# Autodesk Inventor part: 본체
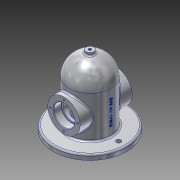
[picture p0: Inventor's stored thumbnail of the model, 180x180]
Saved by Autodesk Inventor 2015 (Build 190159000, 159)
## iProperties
Created: 2019-11
Part Number: 본체
Material: 알루미늄 6061
Document SubType Name: Modeling
Designer: Line503_02
Density: 2.7 g/cm^3
Appearance: 알루미늄 - 평지
Mass: 1106.12 g
Surface Area: 883.263 cm^2
Volume: 409.676 cm^3
Author: Line503_02
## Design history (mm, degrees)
sketch "스케치1"
  geometry: C1 r 70 at (0, 0); 1 further point
  constraints: 1 centre point, 1 coincident
  dimensions: "d0" = 140 diameter of C1
extrude "돌출1" new body sketch "스케치1" distance "d1" = 10; taper "d2" = 0 deg
sketch "스케치2"
  geometry: C1 r 40 at (0, 0); 1 further point
  constraints: 1 centre point, 1 coincident
  dimensions: "d3" = 80 diameter of C1
extrude "돌출2" join sketch "스케치2" distance "d4" = 80; taper "d5" = 0 deg
sketch "스케치3"
  geometry: L1 (40, 90)-(-40, 90) reference; L2 (0, 130)-(0, 90); L3 (40, 90)-(0, 90); A1 r 40 centre (0, 90) between (40, 90) and (0, 130); 1 further point
  constraints: 5 end point, 2 point on circle, 1 centre point, 1 midpoint, 1 perpendicular, 1 vertical
revolve "회전1" sketch "스케치3" stored, may be unused: angle "d6" = 90 deg
sketch "스케치4"
  geometry: L1 (-50, 81)-(50, 81); L2 (50, 81)-(50, 50); L3 (50, 50)-(-50, 50); L4 (-50, 50)-(-50, 81); 1 further point
  constraints: 8 end point, 2 parallel, 1 horizontal, 1 perpendicular
  dimensions: "d7" = 50 distance from line of L3 point (0, 0); "d8" = 100 distance of L2.end L3.end; "d9" = 50 distance from line of point (0, 0) L4; "d10" = 62 diameter of L1 L3
revolve "회전2" sketch "스케치4" stored, may be unused: angle "d11" = 90 deg
sketch "스케치5"
  geometry: L1 (40, 10)-(40, 90) reference; L2 (0, 0)-(0, 120); L3 (0, 0)-(30, 0); L4 (30, 0)-(30, 90); A1 r 40 centre (0, 90) between (40, 90) and (-40, 90) reference; A2 r 30 centre (0, 90) between (30, 90) and (0, 120)
  constraints: 6 end point, 2 point on circle, 1 centre point, 1 horizontal, 1 parallel, 1 vertical
  dimensions: "d12" = 10 distance between parallel lines of L1 L4; "d13" = 10 radial gap between concentric circles of A1 A2
revolve "회전3" sketch "스케치5" stored, may be unused: angle "d14" = 90 deg
hole "구멍1" diameter "d17" = 33; stored, may be unused: countersink angle "d21" = 90 deg, drill point angle "d23" = 118 deg; dims "d15" = 10, "d16" = 10, "d18" = 6, "d19" = 40, "d20" = 15, "d22" = 37
sketch "스케치6"
  geometry: C1 r 31 at (0, 0) reference; 2 further points
  constraints: 1 vertical alignment
  dimensions: "d24" = 26 distance of point (0, 26) C1.centre
hole "구멍2" sketch "스케치6" at (0, 26) diameter "d25" = 3.242; stored, may be unused: countersink angle "d29" = 90 deg, drill point angle "d31" = 118 deg; dims "d26" = 8, "d27" = 40, "d28" = 15, "d30" = 10
sketch "스케치7"
  geometry: C1 r 4.5 at (-55, 0); C2 r 4.5 at (55, 0); 1 further point
  constraints: 3 horizontal alignment, 2 centre point
  dimensions: "d35" = 55 distance of C1.centre point (0, 0); "d36" = 55 distance of C2.centre point (0, 0) (= d35); "d37" = 9 diameter of C1; "d38" = 9 diameter of C2
extrude "돌출3" cut sketch "스케치7" distance "d39" = 80; taper "d40" = 0 deg
node "작업 평면1"
sketch "스케치8"
  geometry: L1 (-70, -10)-(70, -10) reference; 2 further points
  constraints: 1 vertical alignment, 1 other
  dimensions: "d41" = 50 distance from line of point (0, 40) L1
feature "엠보싱1" sketch "스케치8" dims "d42" = 0.5, "d43" = 0
node "작업 평면2"
sketch "스케치9"
  geometry: C1 r 7.5 at (0, 0); 1 further point
  constraints: 1 centre point, 1 coincident
  dimensions: "d45" = 15 diameter of C1
extrude "돌출4" join sketch "스케치9" stored distance "d46" = 80; taper "d47" = 0 deg
hole "구멍3" diameter "d50" = 5.188; stored, may be unused: countersink angle "d54" = 90 deg, drill point angle "d56" = 118 deg; dims "d48" = 10, "d49" = 10, "d51" = 12, "d52" = 40, "d53" = 15, "d55" = 16
fillet "모깎기1" dims "d57" = 3
fillet "모깎기2" dims "d58" = 0.3
chamfer "모따기1" distance "d59" = 1; stored, may be unused: second distance "d60" = 2, angle "d61" = 45 deg
node "솔리드1"
pattern_circular "원형 패턴1" dims angle "d33" = 360 deg
mirror "대칭1"
other parameters: "d44" = -135
